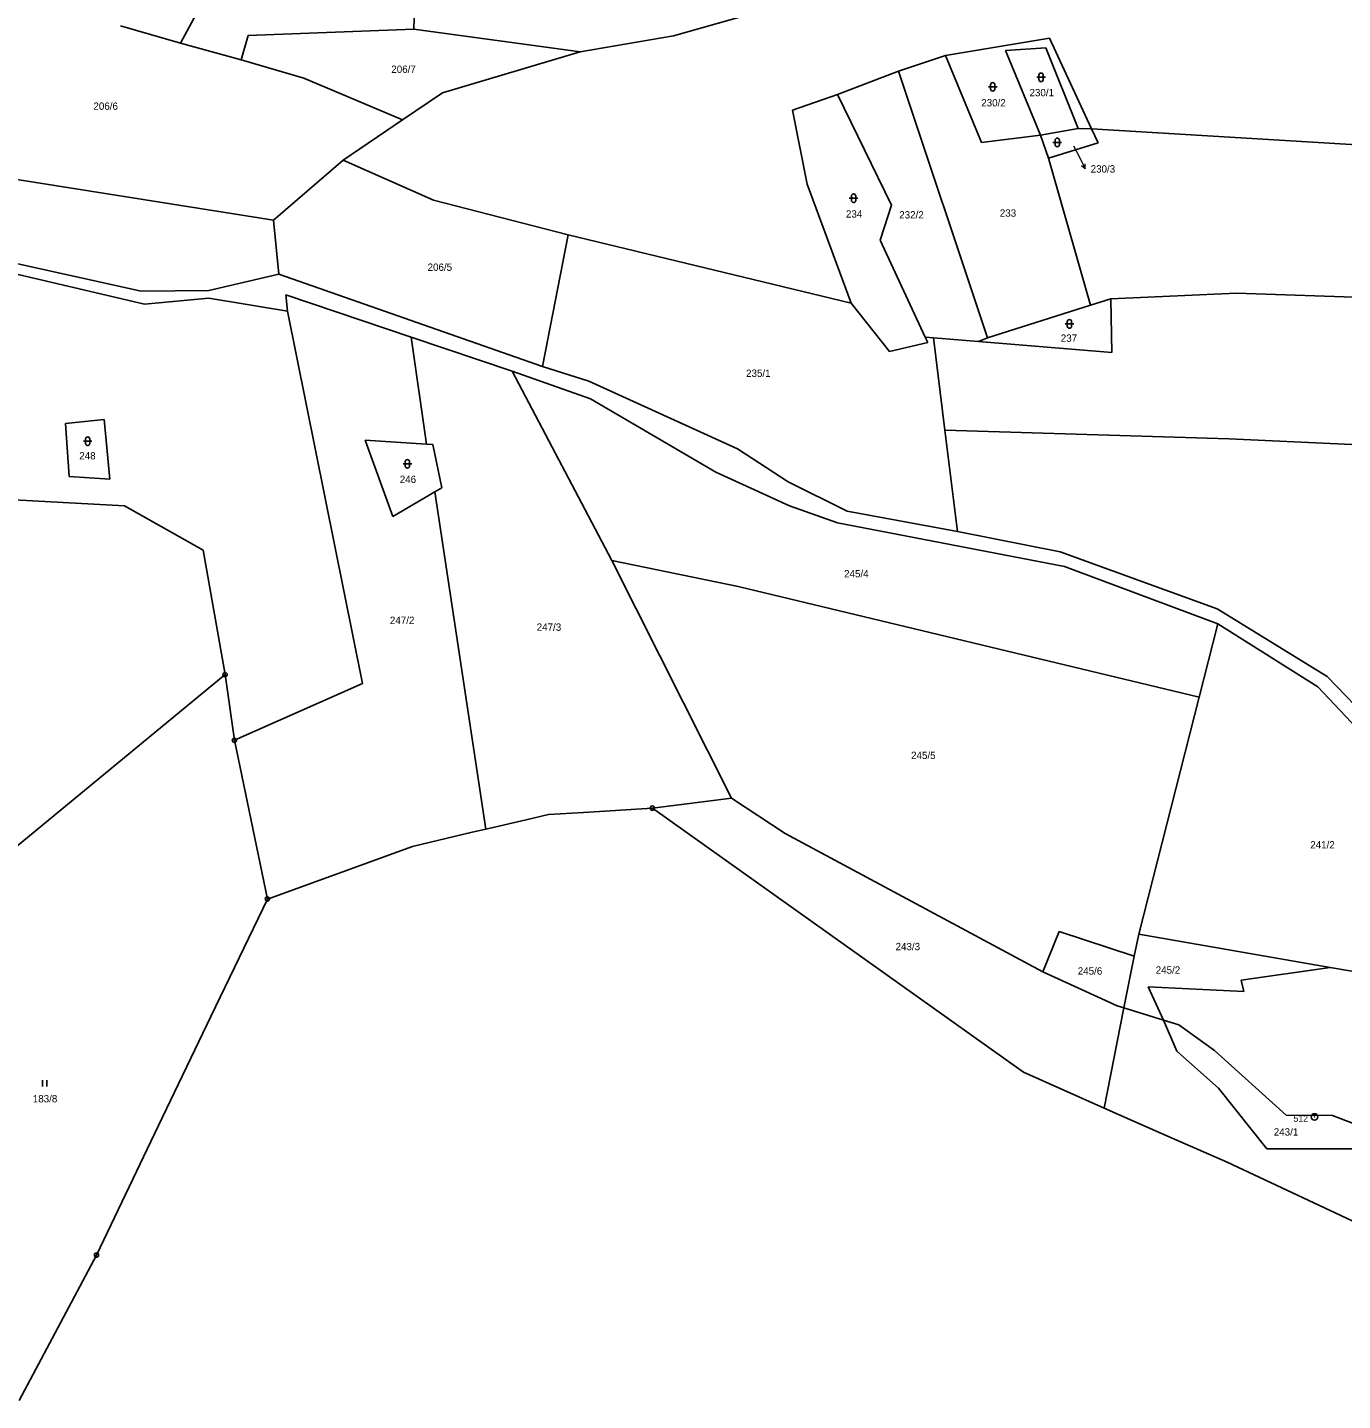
# Model space of a CAD drawing. Extents: x -765428 to -762163, y -1107632 to -1104975.
# Drawn here: x -762745.6 to -762440.6, y -1106381.7 to -1106063.3 of the extents above; entities that cross this region are included whole.
import ezdxf
from ezdxf.enums import TextEntityAlignment as Align

# ---------------------------------------------------------------- set-up
doc = ezdxf.new("R2010")
doc.units = 0
doc.header["$LTSCALE"] = 0.68
for name, color, linetype, lineweight in [('1', 7, 'Continuous', 25), ('3', 7, 'Continuous', 25), ('7', 7, 'Continuous', 13), ('8', 7, 'Continuous', 25)]:
    doc.layers.add(name, color=color, linetype=linetype, lineweight=lineweight)
doc.layers.add('2', color=7, linetype='Continuous')

msp = doc.modelspace()

# ---------------------------------------------------------------- linework, layer by layer
at = {"layer": '1'}
for p, q in [((-762655.06, -1106030.48), (-762655.98, -1106063.74)), ((-762705.51, -1106058.42), (-762710.13, -1106066.98)), ((-762595.78, -1106065.29), (-762569.46, -1106057.84)), ((-762710.13, -1106066.98), (-762724, -1106062.94)), ((-762655.98, -1106063.74), (-762694.41, -1106065.19)), ((-762655.98, -1106063.74), (-762617.43, -1106068.97)), ((-762696.05, -1106070.87), (-762710.13, -1106066.98)), ((-762694.41, -1106065.19), (-762696.05, -1106070.87)), ((-762617.43, -1106068.97), (-762595.78, -1106065.29)), ((-762508.58, -1106065.83), (-762532.65, -1106069.81)), ((-762498.78, -1106086.88), (-762508.58, -1106065.83)), ((-762681.48, -1106075.08), (-762696.05, -1106070.87)), ((-762649.34, -1106078.52), (-762617.43, -1106068.97)), ((-762543.56, -1106073.48), (-762532.65, -1106069.81)), ((-762532.65, -1106069.81), (-762524.34, -1106090.01)), ((-762509.42, -1106068.04), (-762518.78, -1106068.67)), ((-762518.78, -1106068.67), (-762510.63, -1106088.28)), ((-762509.42, -1106068.04), (-762501.88, -1106086.76)), ((-762543.56, -1106073.48), (-762557.72, -1106078.91)), ((-762522.91, -1106135.3), (-762543.56, -1106073.48)), ((-762681.48, -1106075.08), (-762658.59, -1106084.77)), ((-762658.59, -1106084.77), (-762649.34, -1106078.52)), ((-762568.13, -1106082.53), (-762564.78, -1106099.7)), ((-762672.4, -1106094.12), (-762658.59, -1106084.77)), ((-762510.63, -1106088.28), (-762501.88, -1106086.76)), ((-762501.88, -1106086.76), (-762498.78, -1106086.88)), ((-762406.49, -1106092.38), (-762498.78, -1106086.88)), ((-762497.28, -1106090.11), (-762498.78, -1106086.88)), ((-762524.34, -1106090.01), (-762510.63, -1106088.28)), ((-762510.63, -1106088.28), (-762508.81, -1106093.67)), ((-762508.81, -1106093.67), (-762497.28, -1106090.11)), ((-762672.4, -1106094.12), (-762688.52, -1106108.04)), ((-762651.44, -1106103.42), (-762672.4, -1106094.12)), ((-762508.81, -1106093.67), (-762499.05, -1106127.74)), ((-762748.57, -1106098.55), (-762688.52, -1106108.04)), ((-762564.78, -1106099.7), (-762554.56, -1106127.25)), ((-762620.21, -1106111.4), (-762651.44, -1106103.42)), ((-762547.85, -1106112.67), (-762545.2, -1106104.55)), ((-762688.52, -1106108.04), (-762687.28, -1106120.54)), ((-762626.15, -1106141.95), (-762620.21, -1106111.4)), ((-762620.21, -1106111.4), (-762554.56, -1106127.25)), ((-762718.45, -1106127.47), (-762775.71, -1106114.08)), ((-762719.27, -1106124.46), (-762770.42, -1106113.12)), ((-762547.85, -1106112.67), (-762537.35, -1106135.12)), ((-762687.28, -1106120.54), (-762703.54, -1106124.33)), ((-762687.28, -1106120.54), (-762626.15, -1106141.95)), ((-762703.54, -1106124.33), (-762719.27, -1106124.46)), ((-762685.68, -1106125.33), (-762685.33, -1106129.1)), ((-762494.28, -1106126.23), (-762465.16, -1106124.96)), ((-762465.16, -1106124.96), (-762374.2, -1106128.04)), ((-762703.54, -1106126.1), (-762718.45, -1106127.47)), ((-762685.33, -1106129.1), (-762703.54, -1106126.1)), ((-762554.56, -1106127.25), (-762545.63, -1106138.5)), ((-762522.91, -1106135.3), (-762499.05, -1106127.74)), ((-762499.05, -1106127.74), (-762494.28, -1106126.23)), ((-762494.28, -1106126.23), (-762494.06, -1106138.69)), ((-762685.33, -1106129.1), (-762667.92, -1106215.48)), ((-762633.17, -1106143.04), (-762656.63, -1106135.13)), ((-762545.63, -1106138.5), (-762536.76, -1106136.38)), ((-762535.48, -1106135.28), (-762537.35, -1106135.12)), ((-762537.35, -1106135.12), (-762536.76, -1106136.38)), ((-762535.48, -1106135.28), (-762532.81, -1106156.74)), ((-762525, -1106136.17), (-762535.48, -1106135.28)), ((-762525, -1106136.17), (-762522.91, -1106135.3)), ((-762494.06, -1106138.69), (-762525, -1106136.17)), ((-762615.02, -1106149.47), (-762633.17, -1106143.04)), ((-762633.17, -1106143.04), (-762610.03, -1106186.95)), ((-762615.43, -1106145.32), (-762626.15, -1106141.95)), ((-762580.9, -1106161.03), (-762615.43, -1106145.32)), ((-762585.91, -1106166.42), (-762615.02, -1106149.47)), ((-762727.84, -1106154.27), (-762736.8, -1106155.14)), ((-762736.8, -1106155.14), (-762735.97, -1106167.47)), ((-762726.5, -1106168.11), (-762727.84, -1106154.27)), ((-762532.81, -1106156.74), (-762529.89, -1106180.21)), ((-762466.9, -1106158.74), (-762532.81, -1106156.74)), ((-762653.04, -1106159.93), (-762667.28, -1106159.06)), ((-762667.28, -1106159.06), (-762660.89, -1106176.73)), ((-762651.58, -1106160.02), (-762653.04, -1106159.93)), ((-762649.5, -1106170.06), (-762651.58, -1106160.02)), ((-762406.4, -1106161.56), (-762466.9, -1106158.74)), ((-762569.16, -1106168.73), (-762580.9, -1106161.03)), ((-762568.89, -1106174.25), (-762585.91, -1106166.42)), ((-762735.97, -1106167.47), (-762726.5, -1106168.11)), ((-762555.48, -1106175.53), (-762569.16, -1106168.73)), ((-762723.14, -1106174.24), (-762751.57, -1106172.68)), ((-762660.89, -1106176.73), (-762651.15, -1106171.03)), ((-762651.15, -1106171.03), (-762649.5, -1106170.06)), ((-762639.3, -1106249.22), (-762651.15, -1106171.03)), ((-762704.86, -1106184.52), (-762723.14, -1106174.24)), ((-762557.71, -1106178.22), (-762568.89, -1106174.25)), ((-762529.89, -1106180.21), (-762555.48, -1106175.53)), ((-762505.09, -1106188.33), (-762557.71, -1106178.22)), ((-762529.89, -1106180.21), (-762506.05, -1106184.91)), ((-762699.78, -1106213.38), (-762704.86, -1106184.52)), ((-762506.05, -1106184.91), (-762469.65, -1106198.16)), ((-762580.76, -1106192.97), (-762610.03, -1106186.95)), ((-762582.27, -1106242.06), (-762610.03, -1106186.95)), ((-762469.47, -1106201.63), (-762505.09, -1106188.33)), ((-762473.82, -1106218.63), (-762580.76, -1106192.97)), ((-762469.65, -1106198.16), (-762444.17, -1106213.85)), ((-762473.82, -1106218.63), (-762469.47, -1106201.63)), ((-762446.28, -1106216.25), (-762469.47, -1106201.63)), ((-762699.78, -1106213.38), (-762752.7, -1106256.98)), ((-762697.61, -1106228.63), (-762699.78, -1106213.38)), ((-762444.17, -1106213.85), (-762423.97, -1106234.8)), ((-762667.92, -1106215.48), (-762697.61, -1106228.63)), ((-762428.1, -1106235.54), (-762446.28, -1106216.25)), ((-762487.84, -1106273.58), (-762473.82, -1106218.63)), ((-762689.96, -1106265.45), (-762697.61, -1106228.63)), ((-762600.67, -1106244.36), (-762582.27, -1106242.06)), ((-762582.27, -1106242.06), (-762569.85, -1106250.26)), ((-762629.96, -1106247.05), (-762624.74, -1106245.84)), ((-762624.74, -1106245.84), (-762616.65, -1106245.34)), ((-762616.65, -1106245.34), (-762600.67, -1106244.36)), ((-762514.59, -1106305.6), (-762600.67, -1106244.36)), ((-762642.45, -1106249.96), (-762639.3, -1106249.22)), ((-762639.3, -1106249.22), (-762629.96, -1106247.05)), ((-762656.34, -1106253.25), (-762642.45, -1106249.96)), ((-762569.85, -1106250.26), (-762510.08, -1106282.35)), ((-762656.34, -1106253.25), (-762689.96, -1106265.45)), ((-762703.05, -1106292.7), (-762689.96, -1106265.45)), ((-762510.08, -1106282.35), (-762506.34, -1106272.96)), ((-762506.34, -1106272.96), (-762488.94, -1106278.7)), ((-762487.84, -1106273.58), (-762488.94, -1106278.7)), ((-762443.44, -1106281.29), (-762487.84, -1106273.58)), ((-762488.94, -1106278.7), (-762491.3, -1106290.67)), ((-762443.44, -1106281.29), (-762464.07, -1106284.22)), ((-762391.9, -1106290.04), (-762443.44, -1106281.29)), ((-762510.08, -1106282.35), (-762492.84, -1106290.19)), ((-762464.07, -1106284.22), (-762463.49, -1106286.91)), ((-762485.67, -1106285.78), (-762482.11, -1106293.55)), ((-762463.49, -1106286.91), (-762485.67, -1106285.78)), ((-762491.3, -1106290.67), (-762495.89, -1106313.96)), ((-762492.84, -1106290.19), (-762491.3, -1106290.67)), ((-762491.3, -1106290.67), (-762482.11, -1106293.55)), ((-762703.05, -1106292.7), (-762716.12, -1106319.91)), ((-762482.11, -1106293.55), (-762478.98, -1106300.73)), ((-762482.11, -1106293.55), (-762478.51, -1106294.61)), ((-762478.51, -1106294.61), (-762470.28, -1106300.53)), ((-762478.98, -1106300.73), (-762469.37, -1106309.26)), ((-762470.28, -1106300.53), (-762453.64, -1106315.55)), ((-762495.89, -1106313.96), (-762514.59, -1106305.6)), ((-762469.37, -1106309.26), (-762458.11, -1106323.37)), ((-762495.89, -1106313.96), (-762482.53, -1106319.8)), ((-762453.64, -1106315.55), (-762442.9, -1106315.59)), ((-762442.9, -1106315.59), (-762436.26, -1106318.17)), ((-762716.12, -1106319.91), (-762729.6, -1106347.98)), ((-762482.53, -1106319.8), (-762467.35, -1106326.43)), ((-762458.11, -1106323.37), (-762426.94, -1106323.33)), ((-762424.77, -1106346.48), (-762467.35, -1106326.43)), ((-762747.53, -1106381.72), (-762729.6, -1106347.98))]:
    msp.add_line(p, q, dxfattribs=at)
for points in [[(-762545.2, -1106104.55), (-762557.72, -1106078.91), (-762568.13, -1106082.53)], [(-762653.04, -1106159.93), (-762656.63, -1106135.13), (-762685.68, -1106125.33)]]:
    msp.add_lwpolyline(points, dxfattribs=at)
at = {"layer": '3'}
for p, q in [((-762511.011, -1106074.401), (-762511.011, -1106075.402)), ((-762510.009, -1106075.402), (-762510.009, -1106074.401)), ((-762522.711, -1106077.111), (-762520.709, -1106077.111)), ((-762522.211, -1106076.611), (-762522.211, -1106077.612)), ((-762521.209, -1106077.612), (-762521.209, -1106076.611)), ((-762511.511, -1106074.901), (-762509.509, -1106074.901)), ((-762507.751, -1106089.981), (-762505.749, -1106089.981)), ((-762507.251, -1106089.481), (-762507.251, -1106090.482)), ((-762506.249, -1106090.482), (-762506.249, -1106089.481)), ((-762555.001, -1106102.931), (-762552.999, -1106102.931)), ((-762554.501, -1106102.431), (-762554.501, -1106103.432)), ((-762553.499, -1106103.432), (-762553.499, -1106102.431)), ((-762504.411, -1106131.571), (-762504.411, -1106132.572)), ((-762503.409, -1106132.572), (-762503.409, -1106131.571)), ((-762504.911, -1106132.071), (-762502.909, -1106132.071)), ((-762732.651, -1106159.281), (-762730.649, -1106159.281)), ((-762732.151, -1106158.781), (-762732.151, -1106159.782)), ((-762731.149, -1106159.782), (-762731.149, -1106158.781)), ((-762658.481, -1106164.521), (-762656.479, -1106164.521)), ((-762657.981, -1106164.021), (-762657.981, -1106165.022)), ((-762656.979, -1106165.022), (-762656.979, -1106164.021)), ((-762742.151, -1106308.93), (-762742.151, -1106307.43)), ((-762741.15, -1106308.93), (-762741.15, -1106307.43))]:
    msp.add_line(p, q, dxfattribs=at)
for centre, start, end in [((-762510.51, -1106074.4009), 0, 180), ((-762521.71, -1106076.6109), 0, 180), ((-762510.51, -1106075.4009), 180, 359.98789), ((-762521.71, -1106077.6109), 180, 359.98789), ((-762506.75, -1106089.4809), 0, 180), ((-762506.75, -1106090.4809), 180, 359.98789), ((-762554, -1106102.4309), 0, 180), ((-762554, -1106103.4309), 180, 359.98789), ((-762503.91, -1106131.5709), 0, 180), ((-762503.91, -1106132.5709), 180, 359.98789), ((-762731.65, -1106158.7809), 0, 180), ((-762731.65, -1106159.7809), 180, 359.98789), ((-762657.48, -1106164.0209), 0, 180), ((-762657.48, -1106165.0209), 180, 359.98789)]:
    msp.add_arc(centre, 0.5, start, end, dxfattribs=at)
at = {"layer": '7'}
msp.add_line((-762500.238, -1106096.114), (-762500.246, -1106094.994), dxfattribs=at)
msp.add_lwpolyline([(-762502.96, -1106090.77), (-762501.6, -1106093.44), (-762500.238, -1106096.114), (-762501.138, -1106095.449)], dxfattribs=at)
at = {"layer": '8'}
for centre, radius in [((-762699.78, -1106213.3799), 0.5), ((-762699.78, -1106213.3799), 0.0303), ((-762697.61, -1106228.6299), 0.5), ((-762697.61, -1106228.6299), 0.0303), ((-762600.67, -1106244.3599), 0.5), ((-762600.67, -1106244.3599), 0.0303), ((-762689.96, -1106265.4499), 0.5), ((-762689.96, -1106265.4499), 0.0303), ((-762447.09, -1106315.9598), 0.75), ((-762447.09, -1106315.9598), 0.03), ((-762729.6, -1106347.9799), 0.5), ((-762729.6, -1106347.9799), 0.0303)]:
    msp.add_circle(centre, radius, dxfattribs=at)

# ---------------------------------------------------------------- texts
at = {"layer": '2'}
for s, p in [('206/7', (-762658.37, -1106073.875)), ('230/1', (-762510.34, -1106079.295)), ('206/6', (-762727.47, -1106082.435)), ('230/2', (-762521.53, -1106081.645)), ('206/5', (-762649.96, -1106119.775)), ('245/4', (-762553.35, -1106190.855)), ('247/2', (-762658.71, -1106201.655)), ('247/3', (-762624.65, -1106203.235)), ('245/5', (-762537.81, -1106232.975)), ('241/2', (-762445.22, -1106253.705)), ('243/3', (-762541.41, -1106277.305)), ('245/6', (-762499.15, -1106282.955)), ('245/2', (-762481.07, -1106282.745)), ('243/1', (-762453.68, -1106320.285))]:
    msp.add_text(s, height=1.7, dxfattribs=at).set_placement(p, align=Align.CENTER)
for s, p in [('230/3', (-762499, -1106096.985)), ('234', (-762555.76, -1106107.425)), ('232/2', (-762543.41, -1106107.635)), ('233', (-762520.07, -1106107.225)), ('237', (-762505.93, -1106136.225)), ('235/1', (-762578.93, -1106144.365)), ('248', (-762733.6, -1106163.495)), ('246', (-762659.26, -1106168.965)), ('183/8', (-762744.38, -1106312.585))]:
    msp.add_text(s, height=1.7, dxfattribs=at).set_placement(p)
at = {"layer": '8'}
msp.add_text('512', height=1.5, dxfattribs=at).set_placement((-762448.589, -1106317.077), align=Align.RIGHT)

doc.saveas('drawing.dxf')
